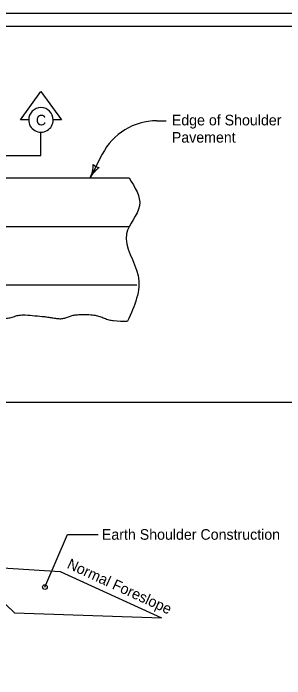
# Model space of a CAD drawing. Extents: x 10133 to 81668, y 7924 to 12229.
# Drawn here: x 11808 to 12217, y 8940 to 9944 of the extents above; entities that cross this region are included whole.
import ezdxf

# ---------------------------------------------------------------- set-up
doc = ezdxf.new("R2010")
doc.units = 0
for name, color, linetype in [('dsnTextFinalPlan', 7, 'Continuous'), ('Level 1', 7, 'Continuous'), ('Level 4', 7, 'Continuous'), ('Level 6', 7, 'Continuous'), ('Level 7', 7, 'Continuous'), ('SheetBorder', 7, 'Continuous')]:
    doc.layers.add(name, color=color, linetype=linetype)

msp = doc.modelspace()

# ---------------------------------------------------------------- linework, layer by layer
at = {"layer": 'dsnTextFinalPlan'}
for p, q in [((11940, 9727.4), (11923.7, 9695.6)), ((10368.6, 9695.6), (11982.4, 9695.6)), ((10368.9, 9622), (11982.7, 9622)), ((11743.8, 9109.9), (11878.7, 9101.5)), ((11878.7, 9101.5), (12031.2, 9031.6)), ((11778.9, 9068.5), (11809.4, 9038.8)), ((11809.4, 9038.8), (12031.2, 9031.6))]:
    msp.add_line(p, q, dxfattribs=at)
for points in [[(11982.4, 9695.6), (11998.2, 9653.6), (11978.6, 9611), (11996.1, 9548.4), (11980.3, 9479.2)], [(11700.5, 9482.9), (11702.5, 9483), (11710.1, 9483.5), (11717.7, 9484.2), (11725.2, 9485), (11732.8, 9485.9), (11737.5, 9486.9), (11742.2, 9488.3), (11746.9, 9489.7), (11749.2, 9490.2), (11751.6, 9490.4), (11758.1, 9490.4), (11764.7, 9489.8), (11771.3, 9488.7), (11777.8, 9487.6), (11781.8, 9486.7), (11785.8, 9485.4), (11789.8, 9484.3), (11793.8, 9483.6), (11797.3, 9483.6), (11800.9, 9484.1), (11808, 9486), (11815.1, 9488), (11822.3, 9488.7), (11836.8, 9487.8), (11851.4, 9486.5), (11858.1, 9485.6), (11864.8, 9484.6), (11871.5, 9483.7), (11878.2, 9483), (11883.9, 9483.6), (11889.6, 9485.4), (11895.3, 9487.5), (11901, 9488.7), (11908.5, 9489.2), (11916.1, 9489.4), (11927.5, 9488.7), (11931.2, 9488.2), (11938.2, 9486.3), (11945.1, 9483.8), (11952, 9481.4), (11959.1, 9480.2), (11980.3, 9479.2)]]:
    msp.add_spline(points, degree=3, dxfattribs=at)
at = {"layer": 'Level 1'}
msp.add_line((10152.2, 9924.4), (13247.9, 9924.4), dxfattribs=at)
at = {"layer": 'Level 4'}
for p, q in [((10352.3, 9534.1), (11994.3, 9534.1)), ((12307.8, 9356.4), (10152.2, 9356.4))]:
    msp.add_line(p, q, dxfattribs=at)
msp.add_circle((11855.4, 9077.9), 3.54, dxfattribs=at)
at = {"layer": 'Level 6'}
for p, q in [((12024.3, 9781.7), (12038.6, 9781.7)), ((11941.9, 9731.3), (11923.7, 9695.6)), ((11855.4, 9077.9), (11889.6, 9157.3)), ((11889.6, 9157.3), (11936, 9157.3))]:
    msp.add_line(p, q, dxfattribs=at)
for centre, radius, start, end in [((12024.3, 9689.3), 92.4, 90, 152.9341), ((11885.9, 9715), 42.5, 332.9341, 1.0066), ((11939.9, 9727.4), 16.4, 225.2008, 260.6675), ((11961.6, 9676.3), 42.5, 124.8616, 152.9341)]:
    msp.add_arc(centre, radius, start, end, dxfattribs=at)
at = {"layer": 'Level 7'}
for p, q in [((11849.5, 9729.2), (11849.5, 9764.6)), ((11761.4, 9729.2), (11849.5, 9729.2))]:
    msp.add_line(p, q, dxfattribs=at)
msp.add_lwpolyline([(11831.1, 9783.1), (11818.7, 9783.1), (11849.5, 9826.2), (11880.4, 9783.1), (11868, 9783.1)], dxfattribs=at)
for start, end in [(0.0008, 179.9992), (179.9992, 0.0008)]:
    msp.add_arc((11849.5, 9783.1), 18.5, start, end, dxfattribs=at)
at = {"layer": 'SheetBorder'}
msp.add_lwpolyline([(10132.5, 9944), (13267.5, 9944), (13267.5, 7924), (10132.5, 7924)], close=True, dxfattribs=at)

# ---------------------------------------------------------------- texts
at = {"layer": 'Level 6'}
for s, p in [('Edge of Shoulder', (12047, 9774.8)), ('Pavement', (12047, 9748.8)), ('Earth Shoulder Construction', (11941.5, 9149.3))]:
    msp.add_text(s, height=16, dxfattribs=at).set_placement(p)
msp.add_text('Normal Foreslope', height=16, rotation=335.372, dxfattribs=at).set_placement((11887.6, 9107.1))
at = {"layer": 'Level 7'}
msp.add_text('C', height=16, dxfattribs=at).set_placement((11841.9, 9774.8))

doc.saveas('drawing.dxf')
